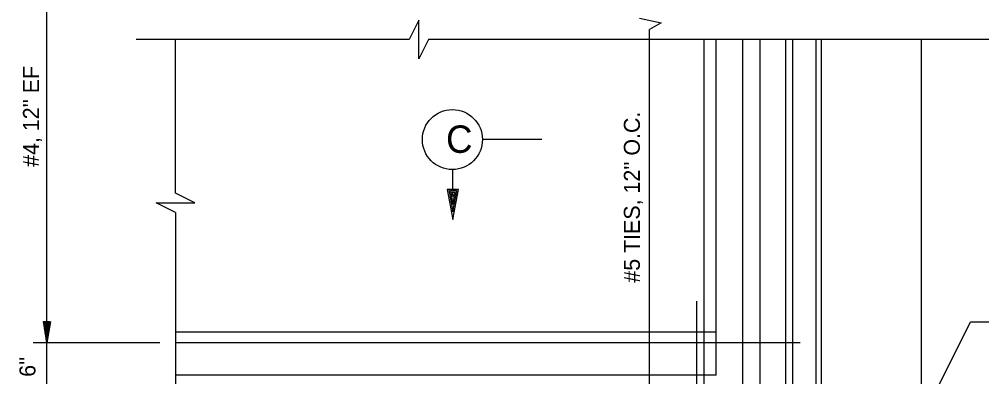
# Model space of a CAD drawing. Extents: x 22369.6 to 22428.3, y 22369.6 to 22415.
# Drawn here: x 22391.45 to 22402.68, y 22400.49 to 22404.66 of the extents above; entities that cross this region are included whole.
import ezdxf

# ---------------------------------------------------------------- set-up
doc = ezdxf.new("R2010")
doc.units = 0
for name, color, linetype in [('Level 1', 7, 'Continuous'), ('Level 10', 7, 'Continuous'), ('Level 2', 7, 'Continuous'), ('Level 3', 7, 'Continuous'), ('Level 4', 7, 'Continuous'), ('Level 7', 7, 'Continuous')]:
    doc.layers.add(name, color=color, linetype=linetype)

msp = doc.modelspace()

# ---------------------------------------------------------------- linework, layer by layer
at = {"layer": 'Level 1'}
for p, q in [((22391.773, 22400.88), (22391.773, 22407.255)), ((22398.687, 22404.67), (22398.942, 22404.618)), ((22398.942, 22404.618), (22398.803, 22404.537)), ((22398.803, 22399.253), (22398.803, 22404.537)), ((22396, 22404.422), (22392.816, 22404.422)), ((22393.273, 22402.627), (22393.273, 22404.422)), ((22404.513, 22404.422), (22396.224, 22404.422)), ((22393.273, 22402.402), (22393.273, 22399.126)), ((22401.087, 22398.198), (22402.551, 22401.125)), ((22402.551, 22401.125), (22402.904, 22401.125)), ((22391.773, 22400.95), (22391.773, 22400.95)), ((22393.091, 22400.88), (22391.611, 22400.88)), ((22391.773, 22400.339), (22391.773, 22400.88)), ((22391.773, 22400.88), (22391.773, 22400.88))]:
    msp.add_line(p, q, dxfattribs=at)
for points in [[(22396.224, 22404.422), (22396.112, 22404.197), (22396.112, 22404.647), (22396, 22404.422)], [(22393.273, 22402.402), (22393.048, 22402.514), (22393.498, 22402.514), (22393.273, 22402.627)], [(22391.814, 22401.13), (22391.773, 22400.88), (22391.732, 22401.13), (22391.802, 22401.13), (22391.773, 22400.95), (22391.745, 22401.119), (22391.79, 22401.119), (22391.773, 22401.016), (22391.758, 22401.108), (22391.777, 22401.108), (22391.773, 22401.086)]]:
    msp.add_lwpolyline(points, dxfattribs=at)
at = {"layer": 'Level 10'}
for p, q in [((22399.442, 22399.89), (22399.442, 22404.422)), ((22399.582, 22400.505), (22399.582, 22404.422)), ((22399.894, 22396.483), (22399.894, 22404.422)), ((22400.096, 22396.483), (22400.096, 22404.422)), ((22400.478, 22396.499), (22400.478, 22404.422)), ((22399.355, 22396.937), (22399.355, 22401.367)), ((22399.582, 22401.005), (22393.273, 22401.005)), ((22400.561, 22400.88), (22393.273, 22400.88)), ((22399.582, 22400.505), (22393.273, 22400.505))]:
    msp.add_line(p, q, dxfattribs=at)
at = {"layer": 'Level 2'}
msp.add_line((22401.978, 22398.755), (22401.978, 22404.422), dxfattribs=at)
at = {"layer": 'Level 3'}
for p, q in [((22397.548, 22403.254), (22396.86, 22403.254)), ((22396.511, 22402.671), (22396.511, 22402.904))]:
    msp.add_line(p, q, dxfattribs=at)
msp.add_lwpolyline([(22396.462, 22402.671), (22396.444, 22402.671), (22396.511, 22402.321), (22396.576, 22402.671), (22396.462, 22402.671), (22396.509, 22402.41), (22396.556, 22402.654), (22396.481, 22402.654), (22396.509, 22402.498), (22396.536, 22402.638), (22396.501, 22402.638), (22396.509, 22402.588), (22396.516, 22402.621)], dxfattribs=at)
msp.add_circle((22396.504, 22403.254), 0.35, dxfattribs=at)
at = {"layer": 'Level 7'}
for p, q in [((22400.394, 22396.255), (22400.394, 22404.422)), ((22400.749, 22395.922), (22400.749, 22404.422)), ((22400.811, 22395.922), (22400.811, 22404.422))]:
    msp.add_line(p, q, dxfattribs=at)

# ---------------------------------------------------------------- texts
at = {"layer": 'Level 3'}
msp.add_text('C', height=0.32, dxfattribs=at).set_placement((22396.43, 22403.099))
at = {"layer": 'Level 4'}
for s, height, p in [("#4, 12'' EF", 0.18667, (22391.68, 22402.936)), ("#5 TIES, 12'' O.C.", 0.18667, (22398.692, 22401.584)), ("6''", 0.1867, (22391.639, 22400.485))]:
    msp.add_text(s, height=height, rotation=90, dxfattribs=at).set_placement(p)

doc.saveas('drawing.dxf')
